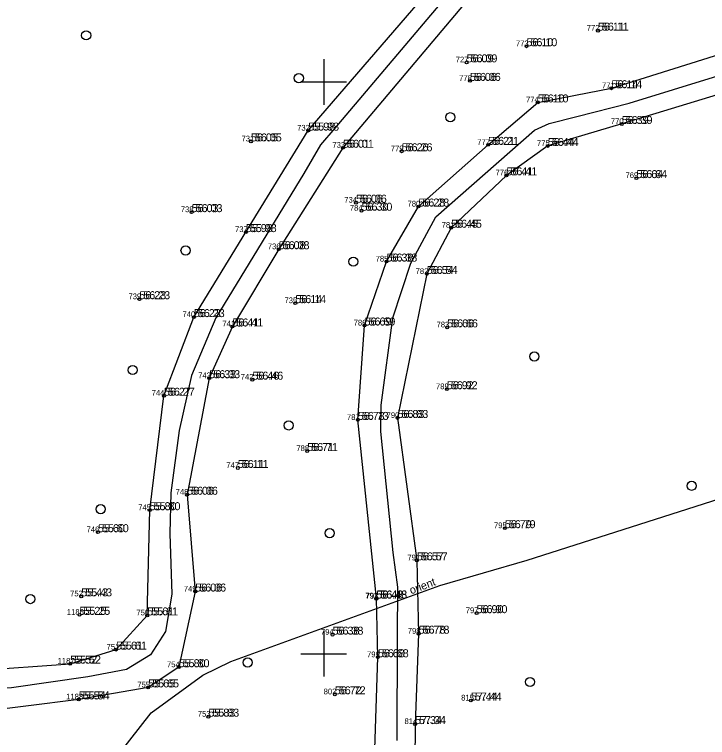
# Model space of a CAD drawing. Extents: x 554846 to 556995, y 6445875 to 6446723.
# Drawn here: x 555323 to 555383.6, y 6446142.7 to 6446205.9 of the extents above; entities that cross this region are included whole.
import ezdxf

# ---------------------------------------------------------------- set-up
doc = ezdxf.new("R2010")
doc.units = 0
for name, color, linetype in [('HALJASTUS', 7, 'Continuous'), ('KORGUS-EH2000', 7, 'Continuous'), ('MOOTKORG-EH2000', 7, 'Continuous'), ('MOOTMPUNKT', 7, 'Continuous'), ('MOOTNR', 7, 'Continuous'), ('SITRASS', 7, 'Continuous'), ('TEE', 7, 'Continuous'), ('VORK', 7, 'Continuous')]:
    doc.layers.add(name, color=color, linetype=linetype)

msp = doc.modelspace()

# ---------------------------------------------------------------- linework, layer by layer
at = {"layer": 'HALJASTUS'}
for centre in [(555329.233, 6446204.078), (555347.828, 6446200.336), (555361.068, 6446196.916), (555337.925, 6446185.258), (555352.591, 6446184.288), (555368.414, 6446175.995), (555333.297, 6446174.811), (555346.94, 6446169.964), (555382.165, 6446164.687), (555330.498, 6446162.64), (555350.519, 6446160.54), (555324.362, 6446154.778), (555343.361, 6446149.232), (555368.038, 6446147.535)]:
    msp.add_circle(centre, 0.4, dxfattribs=at)
at = {"layer": 'KORGUS-EH2000'}
for centre in [(555373.971, 6446204.486), (555367.725, 6446203.123), (555362.491, 6446201.714), (555362.784, 6446200.093), (555375.151, 6446199.451), (555368.709, 6446198.21), (555376.051, 6446196.325), (555348.653, 6446195.747), (555343.64, 6446194.803), (555351.686, 6446194.246), (555364.371, 6446194.497), (555369.591, 6446194.402), (555356.815, 6446193.939), (555365.972, 6446191.831), (555377.331, 6446191.593), (555352.822, 6446189.442), (555358.278, 6446189.106), (555338.458, 6446188.616), (555353.308, 6446188.739), (555361.138, 6446187.251), (555343.195, 6446186.872), (555346.065, 6446185.374), (555355.49, 6446184.295), (555359.011, 6446183.209), (555333.884, 6446181.003), (555347.52, 6446180.658), (555338.652, 6446179.437), (555342.016, 6446178.617), (555353.572, 6446178.703), (555360.789, 6446178.54), (555339.999, 6446174.095), (555343.768, 6446173.965), (555360.762, 6446173.13), (555336.036, 6446172.561), (555356.45, 6446170.618), (555352.982, 6446170.446), (555348.559, 6446167.724), (555342.488, 6446166.243), (555338.056, 6446163.903), (555334.787, 6446162.551), (555330.27, 6446160.627), (555365.831, 6446160.978), (555358.144, 6446158.167), (555338.775, 6446155.436), (555328.806, 6446155.015), (555354.599, 6446154.814), (555354.606, 6446154.835), (555363.367, 6446153.547), (555328.647, 6446153.402), (555334.577, 6446153.352), (555350.777, 6446151.668), (555358.301, 6446151.752), (555331.849, 6446150.359), (555354.737, 6446149.692), (555327.837, 6446149.13), (555337.326, 6446148.82), (555334.659, 6446147.055), (555328.586, 6446146.006), (555350.97, 6446146.45), (555362.864, 6446145.909), (555339.92, 6446144.496), (555357.987, 6446143.849)]:
    msp.add_circle(centre, 0.125, dxfattribs=at)
at = {"layer": 'MOOTMPUNKT'}
for centre in [(555373.971, 6446204.486), (555367.725, 6446203.123), (555362.491, 6446201.714), (555362.784, 6446200.093), (555375.151, 6446199.451), (555368.709, 6446198.21), (555376.051, 6446196.325), (555348.653, 6446195.747), (555343.64, 6446194.803), (555351.686, 6446194.246), (555364.371, 6446194.497), (555369.591, 6446194.402), (555356.815, 6446193.939), (555365.972, 6446191.831), (555377.331, 6446191.593), (555352.822, 6446189.442), (555358.278, 6446189.106), (555338.458, 6446188.616), (555353.308, 6446188.739), (555361.138, 6446187.251), (555343.195, 6446186.872), (555346.065, 6446185.374), (555355.49, 6446184.295), (555359.011, 6446183.209), (555333.884, 6446181.003), (555347.52, 6446180.658), (555338.652, 6446179.437), (555342.016, 6446178.617), (555353.572, 6446178.703), (555360.789, 6446178.54), (555339.999, 6446174.095), (555343.768, 6446173.965), (555360.762, 6446173.13), (555336.036, 6446172.561), (555356.45, 6446170.618), (555352.982, 6446170.446), (555348.559, 6446167.724), (555342.488, 6446166.243), (555338.056, 6446163.903), (555334.787, 6446162.551), (555330.27, 6446160.627), (555365.831, 6446160.978), (555358.144, 6446158.167), (555338.775, 6446155.436), (555328.806, 6446155.015), (555354.599, 6446154.814), (555354.606, 6446154.835), (555363.367, 6446153.547), (555328.647, 6446153.402), (555334.577, 6446153.352), (555350.777, 6446151.668), (555358.301, 6446151.752), (555331.849, 6446150.359), (555354.737, 6446149.692), (555327.837, 6446149.13), (555337.326, 6446148.82), (555334.659, 6446147.055), (555328.586, 6446146.006), (555350.97, 6446146.45), (555362.864, 6446145.909), (555339.92, 6446144.496), (555357.987, 6446143.849)]:
    msp.add_circle(centre, 0.125, dxfattribs=at)
at = {"layer": 'SITRASS'}
msp.add_lwpolyline([(555305.763, 6446088.513), (555311.729, 6446098.729), (555315.174, 6446103.591), (555318.557, 6446109.253), (555319.725, 6446114.115), (555320.34, 6446119.408), (555319.91, 6446123.531), (555321.017, 6446127.039), (555334.918, 6446144.825), (555339.434, 6446148.129), (555341.895, 6446149.324), (555360.137, 6446155.971), (555367.799, 6446158.187), (555388.114, 6446164.693), (555397.639, 6446165.994), (555410.433, 6446167.471), (555421.224, 6446169.405), (555430.679, 6446171.973), (555436.583, 6446173.098), (555447.304, 6446175.102), (555466.494, 6446179.217), (555474.824, 6446180.342)], dxfattribs=at)
at = {"layer": 'TEE'}
for points in [[(555247.524, 6446162.12), (555265.475, 6446160.791), (555276.343, 6446159.564), (555286.428, 6446157.676), (555298.359, 6446153.147), (555308.586, 6446150.291), (555319.617, 6446148.545), (555327.837, 6446149.13), (555331.849, 6446150.359), (555334.577, 6446153.352), (555334.787, 6446162.551), (555336.036, 6446172.561), (555338.652, 6446179.437), (555343.195, 6446186.872), (555348.653, 6446195.747), (555359.358, 6446208.204), (555362.003, 6446212.548), (555362.385, 6446223.831), (555370.17, 6446230.713), (555377.982, 6446233.661), (555385.778, 6446233.467)], [(555385.539, 6446229.679), (555377.588, 6446229.894), (555371.935, 6446227.338), (555367.702, 6446222.175), (555366.293, 6446212.406), (555362.231, 6446206.735), (555351.686, 6446194.246), (555346.065, 6446185.374), (555342.016, 6446178.617), (555339.999, 6446174.095), (555338.056, 6446163.903), (555338.775, 6446155.436), (555337.326, 6446148.82), (555334.659, 6446147.055), (555328.586, 6446146.006), (555319.301, 6446144.844), (555307.942, 6446146.593), (555297.144, 6446150.177), (555285.78, 6446154.201), (555276.238, 6446155.855), (555265.443, 6446157.089), (555246.521, 6446158.607)], [(555361.119, 6446207.957), (555350.961, 6446195.962), (555349.721, 6446194.497), (555348.27, 6446191.982), (555340.583, 6446179.379), (555338.433, 6446174.332), (555337.368, 6446169.525), (555336.624, 6446164.085), (555336.563, 6446160.504), (555336.728, 6446155.209), (555336.17, 6446151.941), (555334.847, 6446149.893), (555332.766, 6446148.622), (555329.389, 6446147.99), (555322.706, 6446147.017), (555319.998, 6446146.872), (555316.835, 6446147.079), (555308.374, 6446148.645), (555297.882, 6446151.867), (555287.555, 6446155.584), (555284.904, 6446156.283), (555276.557, 6446157.823), (555265.921, 6446159.199), (555247.573, 6446160.59)], [(555319.047, 6446120.137), (555327.599, 6446116.893), (555334.239, 6446114.918), (555335.355, 6446113.531), (555342.993, 6446115.198), (555350.581, 6446118.824), (555355.246, 6446122.787), (555354.678, 6446129.7), (555354.451, 6446140.741), (555354.737, 6446149.692), (555354.606, 6446154.835), (555352.982, 6446170.446), (555353.572, 6446178.703), (555355.49, 6446184.295), (555358.278, 6446189.106), (555364.371, 6446194.497), (555368.709, 6446198.21), (555375.151, 6446199.451), (555387.148, 6446203.23)], [(555356.43, 6446142.409), (555356.459, 6446151.538), (555356.472, 6446155.809), (555356.08, 6446158.85), (555354.988, 6446169.438), (555355.009, 6446171.734), (555356.052, 6446179.365), (555357.608, 6446184.143), (555359.815, 6446188.197), (555368.428, 6446195.789), (555369.695, 6446196.369), (555372.119, 6446196.984), (555376.703, 6446198.148), (555388.324, 6446201.726)], [(555388.023, 6446199.971), (555376.051, 6446196.325), (555369.591, 6446194.402), (555365.972, 6446191.831), (555361.138, 6446187.251), (555359.011, 6446183.209), (555356.45, 6446170.618), (555358.144, 6446158.167), (555358.301, 6446151.752), (555357.987, 6446143.849), (555357.865, 6446130.39), (555359.29, 6446124.094), (555357.341, 6446118.603), (555353.951, 6446116.697), (555345.675, 6446113.007), (555338.826, 6446110.512), (555332.979, 6446111.543), (555326.115, 6446113.958), (555318.13, 6446116.963)]]:
    msp.add_lwpolyline(points, dxfattribs=at)
at = {"layer": 'VORK'}
for p, q in [((555350, 6446202), (555350, 6446198)), ((555348, 6446200), (555352, 6446200)), ((555350, 6446152), (555350, 6446148)), ((555348, 6446150), (555352, 6446150))]:
    msp.add_line(p, q, dxfattribs=at)

# ---------------------------------------------------------------- texts
at = {"layer": 'KORGUS-EH2000'}
for s, p in [('56.11', (555374.321, 6446204.486)), ('56.10', (555368.075, 6446203.123)), ('56.09', (555362.841, 6446201.714)), ('56.06', (555363.134, 6446200.093)), ('56.14', (555375.501, 6446199.451)), ('56.10', (555369.059, 6446198.21)), ('56.39', (555376.401, 6446196.325)), ('55.98', (555349.003, 6446195.747)), ('56.05', (555343.99, 6446194.803)), ('56.01', (555352.036, 6446194.246)), ('56.21', (555364.721, 6446194.497)), ('56.44', (555369.941, 6446194.402)), ('56.26', (555357.165, 6446193.939)), ('56.41', (555366.322, 6446191.831)), ('56.64', (555377.681, 6446191.593)), ('56.06', (555353.172, 6446189.442)), ('56.28', (555358.628, 6446189.106)), ('56.03', (555338.808, 6446188.616)), ('56.30', (555353.658, 6446188.739)), ('56.45', (555361.488, 6446187.251)), ('55.98', (555343.545, 6446186.872)), ('56.08', (555346.415, 6446185.374)), ('56.38', (555355.84, 6446184.295)), ('56.54', (555359.361, 6446183.209)), ('56.23', (555334.234, 6446181.003)), ('56.14', (555347.87, 6446180.658)), ('56.23', (555339.002, 6446179.437)), ('56.41', (555342.366, 6446178.617)), ('56.69', (555353.922, 6446178.703)), ('56.66', (555361.139, 6446178.54)), ('56.33', (555340.349, 6446174.095)), ('56.46', (555344.118, 6446173.965)), ('56.92', (555361.112, 6446173.13)), ('56.27', (555336.386, 6446172.561)), ('56.83', (555356.8, 6446170.618)), ('56.73', (555353.332, 6446170.446)), ('56.71', (555348.909, 6446167.724)), ('56.11', (555342.838, 6446166.243)), ('56.06', (555338.406, 6446163.903)), ('55.80', (555335.137, 6446162.551)), ('55.60', (555330.62, 6446160.627)), ('56.79', (555366.181, 6446160.978)), ('56.57', (555358.494, 6446158.167)), ('56.06', (555339.125, 6446155.436)), ('55.43', (555329.156, 6446155.015)), ('56.48', (555354.949, 6446154.814)), ('56.48', (555354.956, 6446154.835)), ('56.90', (555363.717, 6446153.547)), ('55.25', (555328.997, 6446153.402)), ('55.61', (555334.927, 6446153.352)), ('56.38', (555351.127, 6446151.668)), ('56.78', (555358.651, 6446151.752)), ('55.61', (555332.199, 6446150.359)), ('55.52', (555328.187, 6446149.13)), ('56.68', (555355.087, 6446149.692)), ('55.80', (555337.676, 6446148.82)), ('55.65', (555335.009, 6446147.055)), ('55.54', (555328.936, 6446146.006)), ('56.72', (555351.32, 6446146.45)), ('57.44', (555363.214, 6446145.909)), ('55.83', (555340.27, 6446144.496)), ('57.34', (555358.337, 6446143.849))]:
    msp.add_text(s, height=0.7, dxfattribs=at).set_placement(p)
at = {"layer": 'MOOTKORG-EH2000'}
for s, p in [('56.11', (555373.971, 6446204.486)), ('56.10', (555367.725, 6446203.123)), ('56.09', (555362.491, 6446201.714)), ('56.06', (555362.784, 6446200.093)), ('56.14', (555375.151, 6446199.451)), ('56.10', (555368.709, 6446198.21)), ('56.39', (555376.051, 6446196.325)), ('55.98', (555348.653, 6446195.747)), ('56.05', (555343.64, 6446194.803)), ('56.01', (555351.686, 6446194.246)), ('56.21', (555364.371, 6446194.497)), ('56.44', (555369.591, 6446194.402)), ('56.26', (555356.815, 6446193.939)), ('56.41', (555365.972, 6446191.831)), ('56.64', (555377.331, 6446191.593)), ('56.06', (555352.822, 6446189.442)), ('56.28', (555358.278, 6446189.106)), ('56.03', (555338.458, 6446188.616)), ('56.30', (555353.308, 6446188.739)), ('56.45', (555361.138, 6446187.251)), ('55.98', (555343.195, 6446186.872)), ('56.08', (555346.065, 6446185.374)), ('56.38', (555355.49, 6446184.295)), ('56.54', (555359.011, 6446183.209)), ('56.23', (555333.884, 6446181.003)), ('56.14', (555347.52, 6446180.658)), ('56.23', (555338.652, 6446179.437)), ('56.41', (555342.016, 6446178.617)), ('56.69', (555353.572, 6446178.703)), ('56.66', (555360.789, 6446178.54)), ('56.33', (555339.999, 6446174.095)), ('56.46', (555343.768, 6446173.965)), ('56.92', (555360.762, 6446173.13)), ('56.27', (555336.036, 6446172.561)), ('56.83', (555356.45, 6446170.618)), ('56.73', (555352.982, 6446170.446)), ('56.71', (555348.559, 6446167.724)), ('56.11', (555342.488, 6446166.243)), ('56.06', (555338.056, 6446163.903)), ('55.80', (555334.787, 6446162.551)), ('55.60', (555330.27, 6446160.627)), ('56.79', (555365.831, 6446160.978)), ('56.57', (555358.144, 6446158.167)), ('56.06', (555338.775, 6446155.436)), ('55.43', (555328.806, 6446155.015)), ('56.48', (555354.599, 6446154.814)), ('56.48', (555354.606, 6446154.835)), ('56.90', (555363.367, 6446153.547)), ('55.25', (555328.647, 6446153.402)), ('55.61', (555334.577, 6446153.352)), ('56.38', (555350.777, 6446151.668)), ('56.78', (555358.301, 6446151.752)), ('55.61', (555331.849, 6446150.359)), ('55.52', (555327.837, 6446149.13)), ('56.68', (555354.737, 6446149.692)), ('55.80', (555337.326, 6446148.82)), ('55.65', (555334.659, 6446147.055)), ('55.54', (555328.586, 6446146.006)), ('56.72', (555350.97, 6446146.45)), ('57.44', (555362.864, 6446145.909)), ('55.83', (555339.92, 6446144.496)), ('57.34', (555357.987, 6446143.849))]:
    msp.add_text(s, height=0.7, dxfattribs=at).set_placement(p)
at = {"layer": 'MOOTNR'}
for s, p in [('772', (555372.996, 6446204.486)), ('773', (555366.8, 6446203.123)), ('727', (555361.541, 6446201.714)), ('778', (555361.834, 6446200.093)), ('771', (555374.326, 6446199.451)), ('774', (555367.684, 6446198.21)), ('770', (555375.101, 6446196.325)), ('732', (555347.678, 6446195.747)), ('731', (555342.815, 6446194.803)), ('733', (555350.761, 6446194.246)), ('777', (555363.421, 6446194.497)), ('775', (555368.641, 6446194.402)), ('779', (555355.865, 6446193.939)), ('776', (555365.022, 6446191.831)), ('769', (555376.381, 6446191.593)), ('734', (555351.797, 6446189.442)), ('738', (555337.508, 6446188.616)), ('784', (555352.283, 6446188.739)), ('780', (555357.328, 6446189.106)), ('781', (555360.313, 6446187.251)), ('737', (555342.245, 6446186.872)), ('736', (555345.115, 6446185.374)), ('785', (555354.54, 6446184.295)), ('782', (555358.036, 6446183.209)), ('739', (555332.934, 6446181.003)), ('735', (555346.57, 6446180.658)), ('740', (555337.652, 6446179.437)), ('741', (555341.141, 6446178.617)), ('786', (555352.622, 6446178.703)), ('783', (555359.864, 6446178.54)), ('743', (555339.024, 6446174.095)), ('742', (555342.743, 6446173.965)), ('789', (555359.812, 6446173.13)), ('744', (555334.961, 6446172.561)), ('787', (555352.032, 6446170.446)), ('790', (555355.5, 6446170.618)), ('788', (555347.609, 6446167.724)), ('747', (555341.488, 6446166.243)), ('748', (555337.056, 6446163.903)), ('745', (555333.787, 6446162.551)), ('795', (555364.881, 6446160.978)), ('746', (555329.27, 6446160.627)), ('791', (555357.319, 6446158.167)), ('752', (555327.831, 6446155.015)), ('749', (555337.775, 6446155.436)), ('792', (555353.631, 6446154.835)), ('793', (555353.674, 6446154.814)), ('1186', (555327.547, 6446153.402)), ('750', (555333.627, 6446153.352)), ('797', (555362.417, 6446153.547)), ('794', (555349.752, 6446151.668)), ('798', (555357.351, 6446151.752)), ('751', (555331.024, 6446150.359)), ('799', (555353.787, 6446149.692)), ('1187', (555326.737, 6446149.13)), ('754', (555336.301, 6446148.82)), ('755', (555333.709, 6446147.055)), ('802', (555349.995, 6446146.45)), ('1188', (555327.486, 6446146.006)), ('815', (555362.014, 6446145.909)), ('753', (555338.995, 6446144.496)), ('814', (555357.062, 6446143.849))]:
    msp.add_text(s, height=0.5, dxfattribs=at).set_placement(p)
at = {"layer": 'SITRASS'}
msp.add_text('orient', height=0.7, rotation=20.53284, dxfattribs=at).set_placement((555357.652, 6446155.187))

doc.saveas('drawing.dxf')
